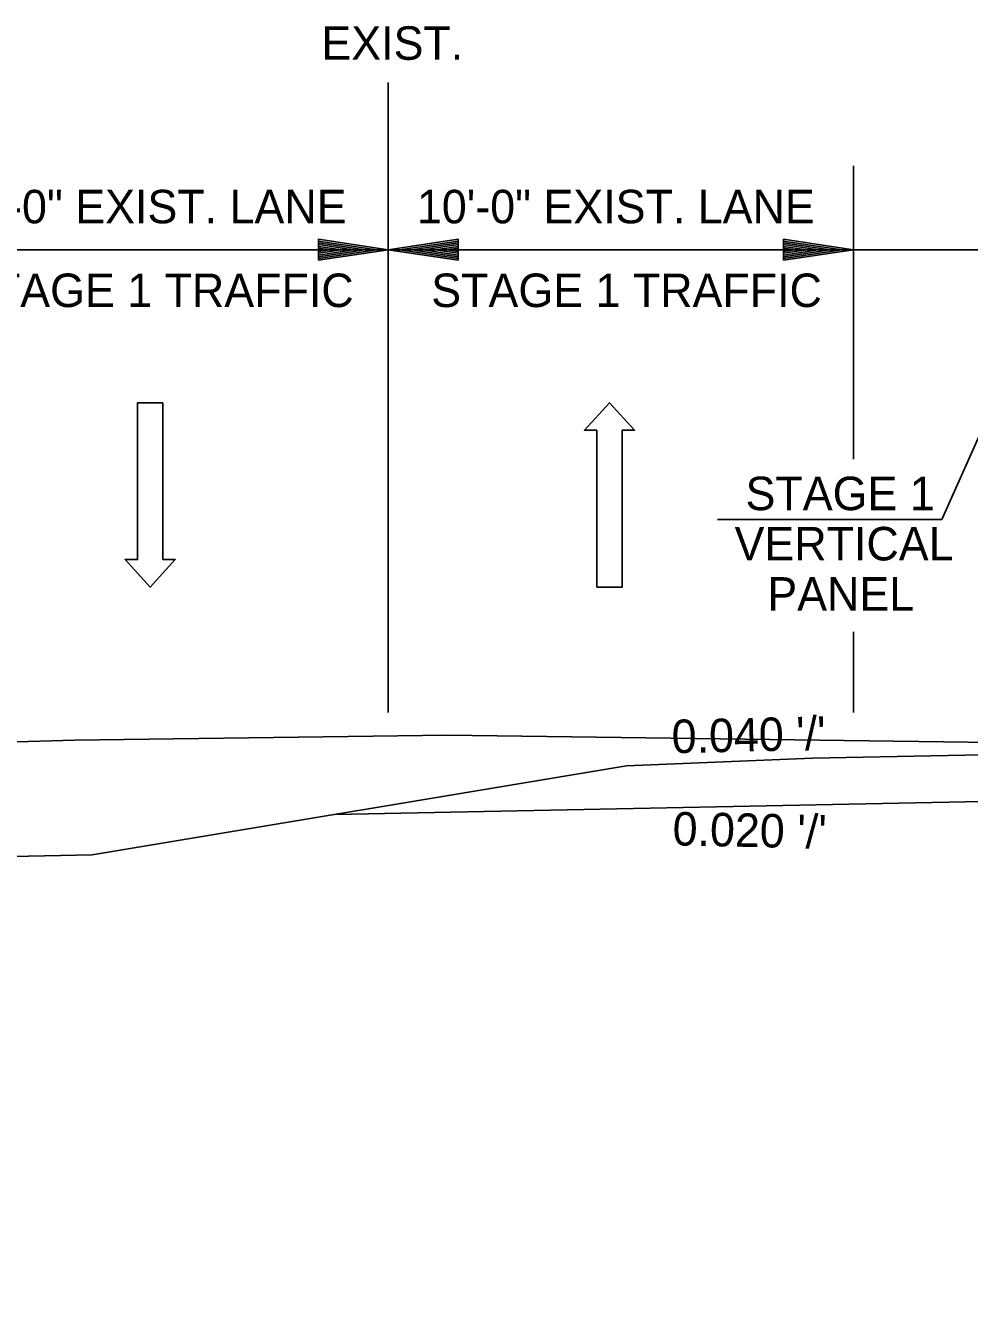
# Model space of a CAD drawing. Extents: x 1807779 to 1818251, y 673292 to 678849.
# Drawn here: x 1813208.6 to 1813411.4, y 676850.2 to 677127.7 of the extents above; entities that cross this region are included whole.
import ezdxf

# ---------------------------------------------------------------- set-up
doc = ezdxf.new("R2010")
doc.units = 0
for name, color, linetype in [('Default', 7, 'Continuous'), ('Dimensions', 7, 'Continuous'), ('EX_TERRAIN', 7, 'Continuous')]:
    doc.layers.add(name, color=color, linetype=linetype)

msp = doc.modelspace()

# ---------------------------------------------------------------- linework, layer by layer
at = {"layer": 'Default'}
for p, q in [((1813487.67, 676972.49), (1813377.69, 676970.29)), ((1813337.69, 676968.69), (1813222.83, 676949.54)), ((1813377.69, 676970.29), (1813337.69, 676968.69)), ((1813487.67, 676962.49), (1813274.97, 676958.23)), ((1813222.83, 676949.54), (1813083.74, 676946.76))]:
    msp.add_line(p, q, dxfattribs=at)
at = {"layer": 'Dimensions'}
for p, q in [((1813286.49, 676980.16), (1813286.49, 677115.58)), ((1813386.49, 677034.6), (1813386.49, 677097.63)), ((1813271.49, 677081.84), (1813286.49, 677079.59)), ((1813271.49, 677081.84), (1813271.49, 677077.34)), ((1813271.49, 677081.84), (1813286.49, 677079.59)), ((1813271.49, 677081.84), (1813271.49, 677077.34)), ((1813301.49, 677081.84), (1813286.49, 677079.59)), ((1813301.49, 677077.34), (1813301.49, 677081.84)), ((1813371.49, 677081.84), (1813386.49, 677079.59)), ((1813371.49, 677081.84), (1813371.49, 677077.34)), ((1813087.87, 677079.59), (1813286.49, 677079.59)), ((1813271.49, 677081.46), (1813283.99, 677079.59)), ((1813271.49, 677081.46), (1813283.99, 677079.59)), ((1813271.49, 677081.08), (1813281.41, 677079.59)), ((1813271.49, 677081.08), (1813281.41, 677079.59)), ((1813271.49, 677080.71), (1813278.91, 677079.59)), ((1813271.49, 677080.71), (1813278.91, 677079.59)), ((1813271.49, 677080.32), (1813276.37, 677079.59)), ((1813271.49, 677080.32), (1813276.37, 677079.59)), ((1813271.49, 677079.94), (1813273.86, 677079.59)), ((1813271.49, 677079.94), (1813273.86, 677079.59)), ((1813271.49, 677077.34), (1813286.49, 677079.59)), ((1813271.49, 677078.85), (1813276.37, 677079.59)), ((1813271.49, 677078.1), (1813281.41, 677079.59)), ((1813271.49, 677077.71), (1813283.99, 677079.59)), ((1813271.49, 677078.47), (1813278.91, 677079.59)), ((1813271.49, 677079.24), (1813273.86, 677079.59)), ((1813271.49, 677077.34), (1813286.49, 677079.59)), ((1813271.49, 677078.85), (1813276.37, 677079.59)), ((1813271.49, 677078.1), (1813281.41, 677079.59)), ((1813271.49, 677077.71), (1813283.99, 677079.59)), ((1813271.49, 677078.47), (1813278.91, 677079.59)), ((1813271.49, 677079.24), (1813273.86, 677079.59)), ((1813286.49, 677079.59), (1813485.64, 677079.59)), ((1813301.49, 677077.34), (1813286.49, 677079.59)), ((1813301.49, 677081.46), (1813289, 677079.59)), ((1813301.49, 677077.71), (1813289, 677079.59)), ((1813301.49, 677081.08), (1813291.58, 677079.59)), ((1813301.49, 677078.1), (1813291.58, 677079.59)), ((1813301.49, 677080.71), (1813294.08, 677079.59)), ((1813301.49, 677078.47), (1813294.08, 677079.59)), ((1813301.49, 677080.32), (1813296.62, 677079.59)), ((1813301.49, 677078.86), (1813296.62, 677079.59)), ((1813301.49, 677079.94), (1813299.12, 677079.59)), ((1813301.49, 677079.24), (1813299.12, 677079.59)), ((1813371.49, 677081.46), (1813383.99, 677079.59)), ((1813371.49, 677081.08), (1813381.41, 677079.59)), ((1813371.49, 677080.71), (1813378.91, 677079.59)), ((1813371.49, 677080.32), (1813376.37, 677079.59)), ((1813371.49, 677079.94), (1813373.86, 677079.59)), ((1813371.49, 677077.34), (1813386.49, 677079.59)), ((1813371.49, 677078.85), (1813376.37, 677079.59)), ((1813371.49, 677078.1), (1813381.41, 677079.59)), ((1813371.49, 677077.71), (1813383.99, 677079.59)), ((1813371.49, 677078.47), (1813378.91, 677079.59)), ((1813371.49, 677079.24), (1813373.86, 677079.59)), ((1813238, 677046.71), (1813238, 677012.99)), ((1813331.34, 677007.07), (1813331.34, 677040.79)), ((1813386.49, 676980.16), (1813386.49, 676997.5))]:
    msp.add_line(p, q, dxfattribs=at)
for points in [[(1813238, 677046.71), (1813232.6, 677046.71), (1813232.6, 677012.99), (1813229.9, 677012.99), (1813235.3, 677007.07), (1813240.7, 677012.99), (1813238, 677012.99)], [(1813331.34, 677007.07), (1813336.74, 677007.07), (1813336.74, 677040.79), (1813339.44, 677040.79), (1813334.04, 677046.71), (1813328.64, 677040.79), (1813331.34, 677040.79)], [(1813415.2, 677043.27), (1813405.52, 677021.62), (1813357.3, 677021.62)]]:
    msp.add_lwpolyline(points, dxfattribs=at)
at = {"layer": 'EX_TERRAIN'}
msp.add_lwpolyline([(1812678.82, 676968.89), (1812734.48, 676935.93), (1812877.87, 676880.69), (1812959.16, 676882.83), (1813053.74, 676934.27), (1813144.45, 676972.05), (1813219.03, 676974.2), (1813299.21, 676975.27), (1813459.2, 676973.13), (1813487.67, 676972.49), (1813516, 676968.9), (1813566.57, 676954.47), (1813614.02, 676941.38), (1813728.73, 676880.37), (1813806.18, 676862.53), (1813861.67, 676857.88), (1813918.12, 676853.04), (1814104.93, 676852.07), (1814246.73, 676850.15)], dxfattribs=at)

# ---------------------------------------------------------------- texts
at = {"layer": 'Dimensions'}
for s, p in [('EXIST.', (1813272.11, 677120.43)), ('10\'-0" EXIST. LANE', (1813191.99, 677085.28)), ('10\'-0" EXIST. LANE', (1813292.65, 677085.28)), ('STAGE 1 TRAFFIC', (1813195.06, 677067.28)), ('STAGE 1 TRAFFIC', (1813295.73, 677067.28)), ('STAGE 1', (1813363.3, 677023.62)), ('VERTICAL ', (1813360.94, 677012.82)), ('PANEL', (1813367.98, 677002.02))]:
    msp.add_text(s, height=7.2, dxfattribs=at).set_placement(p)
for s, rotation, p in [("0.040 '/'", 1.3169, (1813347.5, 676971.36)), ("0.020 '/'", 358.7593, (1813347.56, 676951.58))]:
    msp.add_text(s, height=7.2, rotation=rotation, dxfattribs=at).set_placement(p)

doc.saveas('drawing.dxf')
